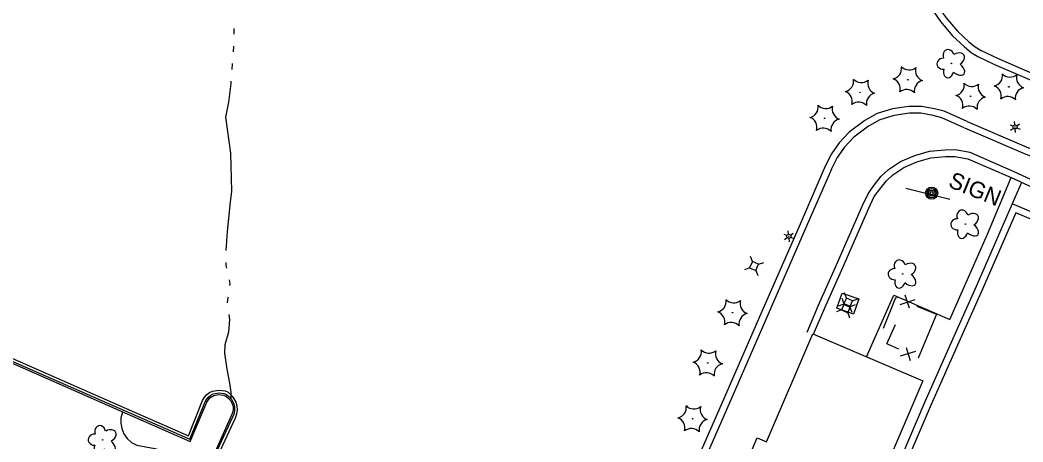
# Model space of a CAD drawing. Extents: x 588843 to 2552415, y 180129 to 269402.
# Drawn here: x 594432.4 to 594799.2, y 185440.6 to 185595.1 of the extents above; entities that cross this region are included whole.
import ezdxf

# ---------------------------------------------------------------- set-up
doc = ezdxf.new("R2010")
doc.units = 0
for name, color, linetype in [('Default', 7, 'Continuous'), ('E_AREA', 7, 'Continuous'), ('E_BLD', 7, 'Continuous'), ('E_DWY', 7, 'Continuous'), ('E_FEN_P', 7, 'Continuous'), ('E_LAND_Vegetation', 7, 'Continuous'), ('E_LTG', 7, 'Continuous'), ('E_MISCPROP', 7, 'Continuous'), ('E_MISCPROP_Planter', 7, 'Continuous'), ('E_PATH_Sidewalk', 7, 'Continuous'), ('E_RDWY_C_and_G', 7, 'Continuous'), ('E_SGN', 7, 'Continuous'), ('E_SGN_Text', 7, 'Continuous'), ('E_UTL_AG_Bold', 7, 'Continuous'), ('E_WTR_P', 7, 'Continuous')]:
    doc.layers.add(name, color=color, linetype=linetype)

# ---------------------------------------------------------------- blocks, each defined once
blk = doc.blocks.new('DTRE_1_1')
at = {"layer": 'Default'}
blk.add_circle((-0.18, 0), 0.183, dxfattribs=at)
for centre, major_axis, ratio in [((-1.87, 5.32), (1.36, -4.98), 0.782863), ((4.06, 2.74), (-5.27, -2.93), 0.691916), ((-5.87, 0.15), (4.93, -0.12), 0.832022), ((-2.49, -5.24), (1.8, 4.86), 0.716896), ((3.54, -3.71), (-5.01, 4.58), 0.560249)]:
    blk.add_ellipse(centre, major_axis=major_axis, ratio=ratio, start_param=1.570796, end_param=4.712389, dxfattribs=at)
blk = doc.blocks.new('LPOL_5')
at = {"layer": 'E_LTG'}
for p, q in [((-13.1, 0), (-4.9, 0)), ((-2.5, 4.3), (-6.6, 11.4)), ((2.5, 4.3), (6.6, 11.4)), ((4.9, 0), (13.1, 0)), ((-6.6, -11.4), (-2.5, -4.3)), ((6.6, -11.4), (2.5, -4.3))]:
    blk.add_line(p, q, dxfattribs=at)
for radius in [4.92, 4.92, 4.92, 0.41]:
    blk.add_circle((0, 0), radius, dxfattribs=at)
blk = doc.blocks.new('POLE_4')
at = {"layer": 'E_MISCPROP'}
for radius in [14.6, 11, 7.32, 3.66]:
    blk.add_circle((0, 0), radius, dxfattribs=at)
blk = doc.blocks.new('PED_4')
at = {"layer": 'E_UTL_AG_Bold'}
for p, q in [((-8.2, 8.2), (-17.5, 17.5)), ((8.2, 8.2), (17.5, 17.5)), ((-8.2, -8.2), (-17.5, -17.5)), ((8.2, -8.2), (17.5, -17.5))]:
    blk.add_line(p, q, dxfattribs=at)
blk.add_lwpolyline([(-8.2, -8.2), (8.2, -8.2), (8.2, 8.2), (-8.2, 8.2)], close=True, dxfattribs=at)
blk = doc.blocks.new('CTRE_5')
at = {"layer": 'E_LAND_Vegetation'}
blk.add_circle((0, 0), 0.733, dxfattribs=at)
for centre, start, end in [((-39.3, 29.4), 280.2067, 5.9716), ((5.9, 49), 220.2113, 305.9762), ((45.4, 19.3), 160.2113, 245.9762), ((-45.4, -19.3), 340.2113, 65.9762), ((-5.9, -49), 40.2113, 125.9762), ((39.5, -29.6), 100.2511, 185.9272)]:
    blk.add_arc(centre, 25.8, start, end, dxfattribs=at)
blk = doc.blocks.new('DTRE_5')
at = {"layer": 'E_LAND_Vegetation'}
blk.add_circle((-0.6, 0), 0.601, dxfattribs=at)
for centre, major_axis, ratio in [((-6.1, 17.5), (4.5, -16.3), 0.782863), ((13.3, 9), (-17.3, -9.6), 0.691916), ((-19.3, 0.5), (16.2, -0.4), 0.832022), ((-8.2, -17.2), (5.9, 15.9), 0.716896), ((11.6, -12.2), (-16.4, 15), 0.560249)]:
    blk.add_ellipse(centre, major_axis=major_axis, ratio=ratio, start_param=1.570796, end_param=4.712389, dxfattribs=at)
blk = doc.blocks.new('SIGN_4')
at = {"layer": 'E_SGN'}
blk.add_text('SIGN', height=39.37, dxfattribs=at).set_placement((-56.1, -19.7))

msp = doc.modelspace()

# ---------------------------------------------------------------- linework, layer by layer
at = {"layer": 'E_AREA'}
msp.add_lwpolyline([(594737.24, 185487.43), (594731.14, 185489.57), (594733.1, 185495.14), (594739.2, 185492.99)], close=True, dxfattribs=at)
at = {"layer": 'E_BLD'}
msp.add_lwpolyline([(594720.92, 185371.72), (594679.49, 185389.41), (594702.02, 185442.16), (594705.46, 185440.69), (594722.35, 185480.22), (594762.62, 185463.02), (594741.76, 185414.17), (594739.47, 185415.15)], close=True, dxfattribs=at)
at = {"layer": 'E_DWY'}
for points in [[(594758.54, 185613.9), (594761.35, 185607.26), (594764.85, 185600.52), (594769.06, 185594.5), (594773.4, 185589.27), (594777.78, 185585.25), (594780.27, 185583.21), (594782.7, 185581.69), (594788.84, 185578.81), (594809.25, 185570), (594815.51, 185567.18), (594838.49, 185557.33), (594865.68, 185545.35)], [(594760.84, 185614.87), (594763.61, 185608.32), (594766.99, 185601.82), (594771.05, 185596.02), (594775.22, 185590.99), (594779.42, 185587.14), (594781.73, 185585.24), (594783.9, 185583.89), (594789.86, 185581.09), (594810.26, 185572.28), (594816.52, 185569.47), (594839.49, 185559.62), (594866.69, 185547.64)], [(594778.76, 185557.92), (594770.35, 185561.7), (594766.89, 185562.59), (594762.12, 185563.46), (594757.51, 185563.47), (594751.53, 185562.57), (594745.92, 185560.87), (594741.39, 185558.35), (594735.65, 185554.07), (594732, 185550.1), (594729.15, 185546.1), (594726.85, 185541.54)], [(594777.73, 185555.64), (594769.52, 185559.34), (594766.35, 185560.15), (594761.89, 185560.96), (594757.69, 185560.97), (594752.08, 185560.13), (594746.9, 185558.55), (594742.75, 185556.25), (594737.33, 185552.21), (594733.95, 185548.52), (594731.3, 185544.8), (594729.08, 185540.41)], [(594778.76, 185557.92), (594800.36, 185548.68), (594805.5, 185546.59), (594823.4, 185539.01)], [(594777.78, 185555.62), (594799.4, 185546.37), (594804.54, 185544.28), (594822.42, 185536.71)], [(594720.26, 185480.85), (594724.42, 185490.74), (594731, 185505.46), (594740.51, 185527.25), (594742.66, 185531.73), (594744.83, 185534.66), (594747.39, 185537.93), (594750.05, 185540.39), (594754.47, 185543.36), (594759.61, 185545.53), (594764.99, 185547.07), (594770.69, 185547.61), (594774.52, 185547.64), (594779.72, 185546.72), (594795.86, 185539.7), (594805.16, 185535.4), (594826.41, 185526.46)], [(594722.65, 185480.09), (594726.72, 185489.74), (594733.28, 185504.45), (594742.78, 185526.21), (594744.81, 185530.44), (594746.82, 185533.14), (594749.24, 185536.24), (594751.61, 185538.43), (594755.66, 185541.16), (594760.44, 185543.17), (594765.45, 185544.6), (594770.82, 185545.11), (594774.31, 185545.14), (594778.99, 185544.31), (594794.83, 185537.42), (594804.15, 185533.12), (594825.44, 185524.16)], [(594726.85, 185541.54), (594717.32, 185519.48), (594703.73, 185488.45), (594689.69, 185456.24), (594675.43, 185423.6), (594663.05, 185395.04)], [(594729.14, 185540.55), (594719.61, 185518.48), (594706.02, 185487.45), (594691.98, 185455.24), (594677.73, 185422.6), (594665.34, 185394.04)], [(594838.58, 185509.24), (594809.4, 185521.78), (594795.25, 185527.78), (594782.09, 185497.55), (594774.42, 185480.39), (594763.35, 185455.3), (594745.71, 185414.07), (594738.5, 185397.81)], [(594837.59, 185506.94), (594808.42, 185519.48), (594796.55, 185524.51), (594784.38, 185496.54), (594776.7, 185479.38), (594765.64, 185454.31), (594748, 185413.07), (594740.78, 185396.79)]]:
    msp.add_lwpolyline(points, dxfattribs=at)
at = {"layer": 'E_FEN_P'}
for p, q in [((594754.31, 185490.98), (594759.82, 185492.85)), ((594755.94, 185494.44), (594757.58, 185489.73)), ((594759.85, 185473.75), (594754.28, 185472.09)), ((594758.09, 185470.36), (594756.63, 185475.13))]:
    msp.add_line(p, q, dxfattribs=at)
for points in [[(594748.18, 185482.35), (594752.71, 185493.54), (594753.19, 185493.35)], [(594760.4, 185490.39), (594767.55, 185487.45), (594765.7, 185482.97)], [(594753.79, 185474.57), (594749.39, 185476.58), (594752.54, 185483.66)], [(594765.7, 185482.97), (594760.89, 185471.34), (594760.89, 185471.34)]]:
    msp.add_lwpolyline(points, dxfattribs=at)
at = {"layer": 'E_MISCPROP_Planter'}
msp.add_lwpolyline([(594469.86, 185451.59), (594469.34, 185449.5), (594469.26, 185447.49), (594469.61, 185445.52), (594470.38, 185443.67), (594470.38, 185443.67), (594471.62, 185441.89), (594473.24, 185440.45), (594475.15, 185439.41), (594475.15, 185439.41), (594481.7, 185438.27), (594491.03, 185435.58), (594502.02, 185431.1), (594511.68, 185425.27), (594514.19, 185423.06), (594516.77, 185421.11)], dxfattribs=at)
at = {"layer": 'E_PATH_Sidewalk'}
for points in [[(594742.02, 185471.82), (594751.93, 185494.36), (594772.46, 185485.47), (594786.23, 185516.75), (594794.9, 185537.39)], [(594798.66, 185535.65), (594795.3, 185527.76)]]:
    msp.add_lwpolyline(points, dxfattribs=at)
at = {"layer": 'E_RDWY_C_and_G'}
for points in [[(594421.83, 185473.5), (594468.97, 185452.93), (594494.52, 185441.61), (594500.12, 185455.37), (594500.69, 185456.35), (594501.42, 185457.2), (594501.42, 185457.2), (594502.2, 185457.81), (594503.09, 185458.23), (594503.09, 185458.23), (594505.21, 185458.65), (594505.21, 185458.65), (594507.03, 185458.4), (594507.03, 185458.4), (594507.97, 185457.97), (594508.78, 185457.31), (594508.78, 185457.31), (594509.73, 185456.13), (594510.46, 185454.81), (594510.46, 185454.81), (594510.83, 185453.63), (594510.91, 185452.39), (594510.91, 185452.39), (594510.68, 185451), (594510.17, 185449.68), (594510.17, 185449.68), (594504.42, 185437.35)], [(594422.13, 185474.44), (594469.27, 185453.8), (594494.05, 185442.87), (594499.19, 185455.81), (594499.87, 185456.98), (594500.76, 185457.99), (594500.76, 185457.99), (594501.7, 185458.71), (594502.77, 185459.21), (594502.77, 185459.21), (594505.28, 185459.66), (594505.28, 185459.66), (594507.39, 185459.34), (594507.39, 185459.34), (594508.49, 185458.81), (594509.43, 185458.04), (594509.43, 185458.04), (594510.52, 185456.68), (594511.35, 185455.15), (594511.35, 185455.15), (594511.77, 185453.82), (594511.86, 185452.42), (594511.86, 185452.42), (594511.61, 185450.84), (594511.05, 185449.34), (594511.05, 185449.34), (594505.75, 185437.78)], [(594421.94, 185472.83), (594468.6, 185452.24), (594494.69, 185440.77), (594500.78, 185455.27), (594501.87, 185456.8), (594501.87, 185456.8), (594503.25, 185457.67), (594503.25, 185457.67), (594505.05, 185458.02), (594505.05, 185458.02), (594506.78, 185457.8), (594506.78, 185457.8), (594507.69, 185457.4), (594508.48, 185456.79), (594508.48, 185456.79), (594509.34, 185455.77), (594510.01, 185454.61), (594510.01, 185454.61), (594510.33, 185453.6), (594510.38, 185452.53), (594510.38, 185452.53), (594510.17, 185451.31), (594509.7, 185450.17), (594509.7, 185450.17), (594503.78, 185437.01)]]:
    msp.add_lwpolyline(points, dxfattribs=at)
at = {"layer": 'E_SGN'}
msp.add_line((594756.31, 185533.51), (594772.47, 185529.5), dxfattribs=at)
at = {"layer": 'E_WTR_P'}
for points in [[(594510.56, 185592.03), (594510.58, 185589.88)], [(594510.5, 185585.58), (594510.35, 185583.43)], [(594510.03, 185579.14), (594509.88, 185576.99)], [(594509.56, 185572.7), (594509.51, 185571.9), (594508.69, 185565.03), (594507.56, 185559.5), (594509.42, 185546.35), (594509.55, 185541.78)], [(594509.55, 185541.78), (594509.81, 185532.48), (594509.18, 185527.5), (594508.18, 185517.58), (594507.64, 185510.68)], [(594507.71, 185506.38), (594507.74, 185505.21), (594507.96, 185504.25)], [(594508.85, 185500.04), (594509.14, 185498.5), (594509.04, 185497.92)], [(594508.37, 185493.67), (594508.13, 185491.53)], [(594508.77, 185487.29), (594509.08, 185485.44), (594508.68, 185480.85), (594507.35, 185476.19), (594507.16, 185473.15), (594508.01, 185467.29), (594509.07, 185462.17), (594509.49, 185458.83), (594509.52, 185456.53)]]:
    msp.add_lwpolyline(points, dxfattribs=at)

# ---------------------------------------------------------------- block references
at = {"layer": 'E_LAND_Vegetation', "xscale": 0.15240030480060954, "yscale": 0.15240030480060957, "rotation": 3.4338469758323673}
for name, p in [('DTRE_5', (594773.14, 185579.2)), ('CTRE_5', (594757.1, 185573.24)), ('CTRE_5', (594739.6, 185568.62)), ('CTRE_5', (594780.04, 185567.19)), ('CTRE_5', (594794.04, 185570.65)), ('CTRE_5', (594726.64, 185559.12)), ('DTRE_5', (594778.22, 185520.4)), ('DTRE_5', (594755.3, 185502.18)), ('CTRE_5', (594692.97, 185487.97)), ('CTRE_5', (594683.91, 185469.57)), ('CTRE_5', (594678.38, 185449.14))]:
    msp.add_blockref(name, p, dxfattribs=at)
at = {"layer": 'E_LAND_Vegetation', "xscale": 0.5, "yscale": 0.5}
msp.add_blockref('DTRE_1_1', (594462.73, 185441.41), dxfattribs=at)
at = {"layer": 'E_LTG', "xscale": 0.1524003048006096, "yscale": 0.1524003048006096, "rotation": -23.954644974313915}
for p in [(594796.31, 185555.96), (594713.59, 185515.95)]:
    msp.add_blockref('LPOL_5', p, dxfattribs=at)
at = {"layer": 'E_MISCPROP', "xscale": 0.1524003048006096, "yscale": 0.1524003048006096, "rotation": -23.954644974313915}
msp.add_blockref('POLE_4', (594765.82, 185531.72), dxfattribs=at)
at = {"layer": 'E_SGN_Text', "xscale": 0.1524003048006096, "yscale": 0.15240030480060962, "rotation": -22.11088937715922}
msp.add_blockref('SIGN_4', (594780.55, 185533.74), dxfattribs=at)
at = {"layer": 'E_UTL_AG_Bold', "xscale": 0.15240030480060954, "yscale": 0.15240030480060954, "rotation": -24.15481473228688}
for p in [(594700.87, 185505.05), (594734.48, 185489.6), (594735.25, 185491.66)]:
    msp.add_blockref('PED_4', p, dxfattribs=at)

doc.saveas('drawing.dxf')
